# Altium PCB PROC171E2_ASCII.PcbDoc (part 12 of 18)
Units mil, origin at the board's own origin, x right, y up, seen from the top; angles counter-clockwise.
Board outline 7700 x 2300 mil, 6 copper layers (Top Layer, GND 1, SIG 1, SIG 2, GND 2, Bottom Layer), stack 61.062 mil thick; 938 components, 688 nets, 11933 pads, 1723 vias.
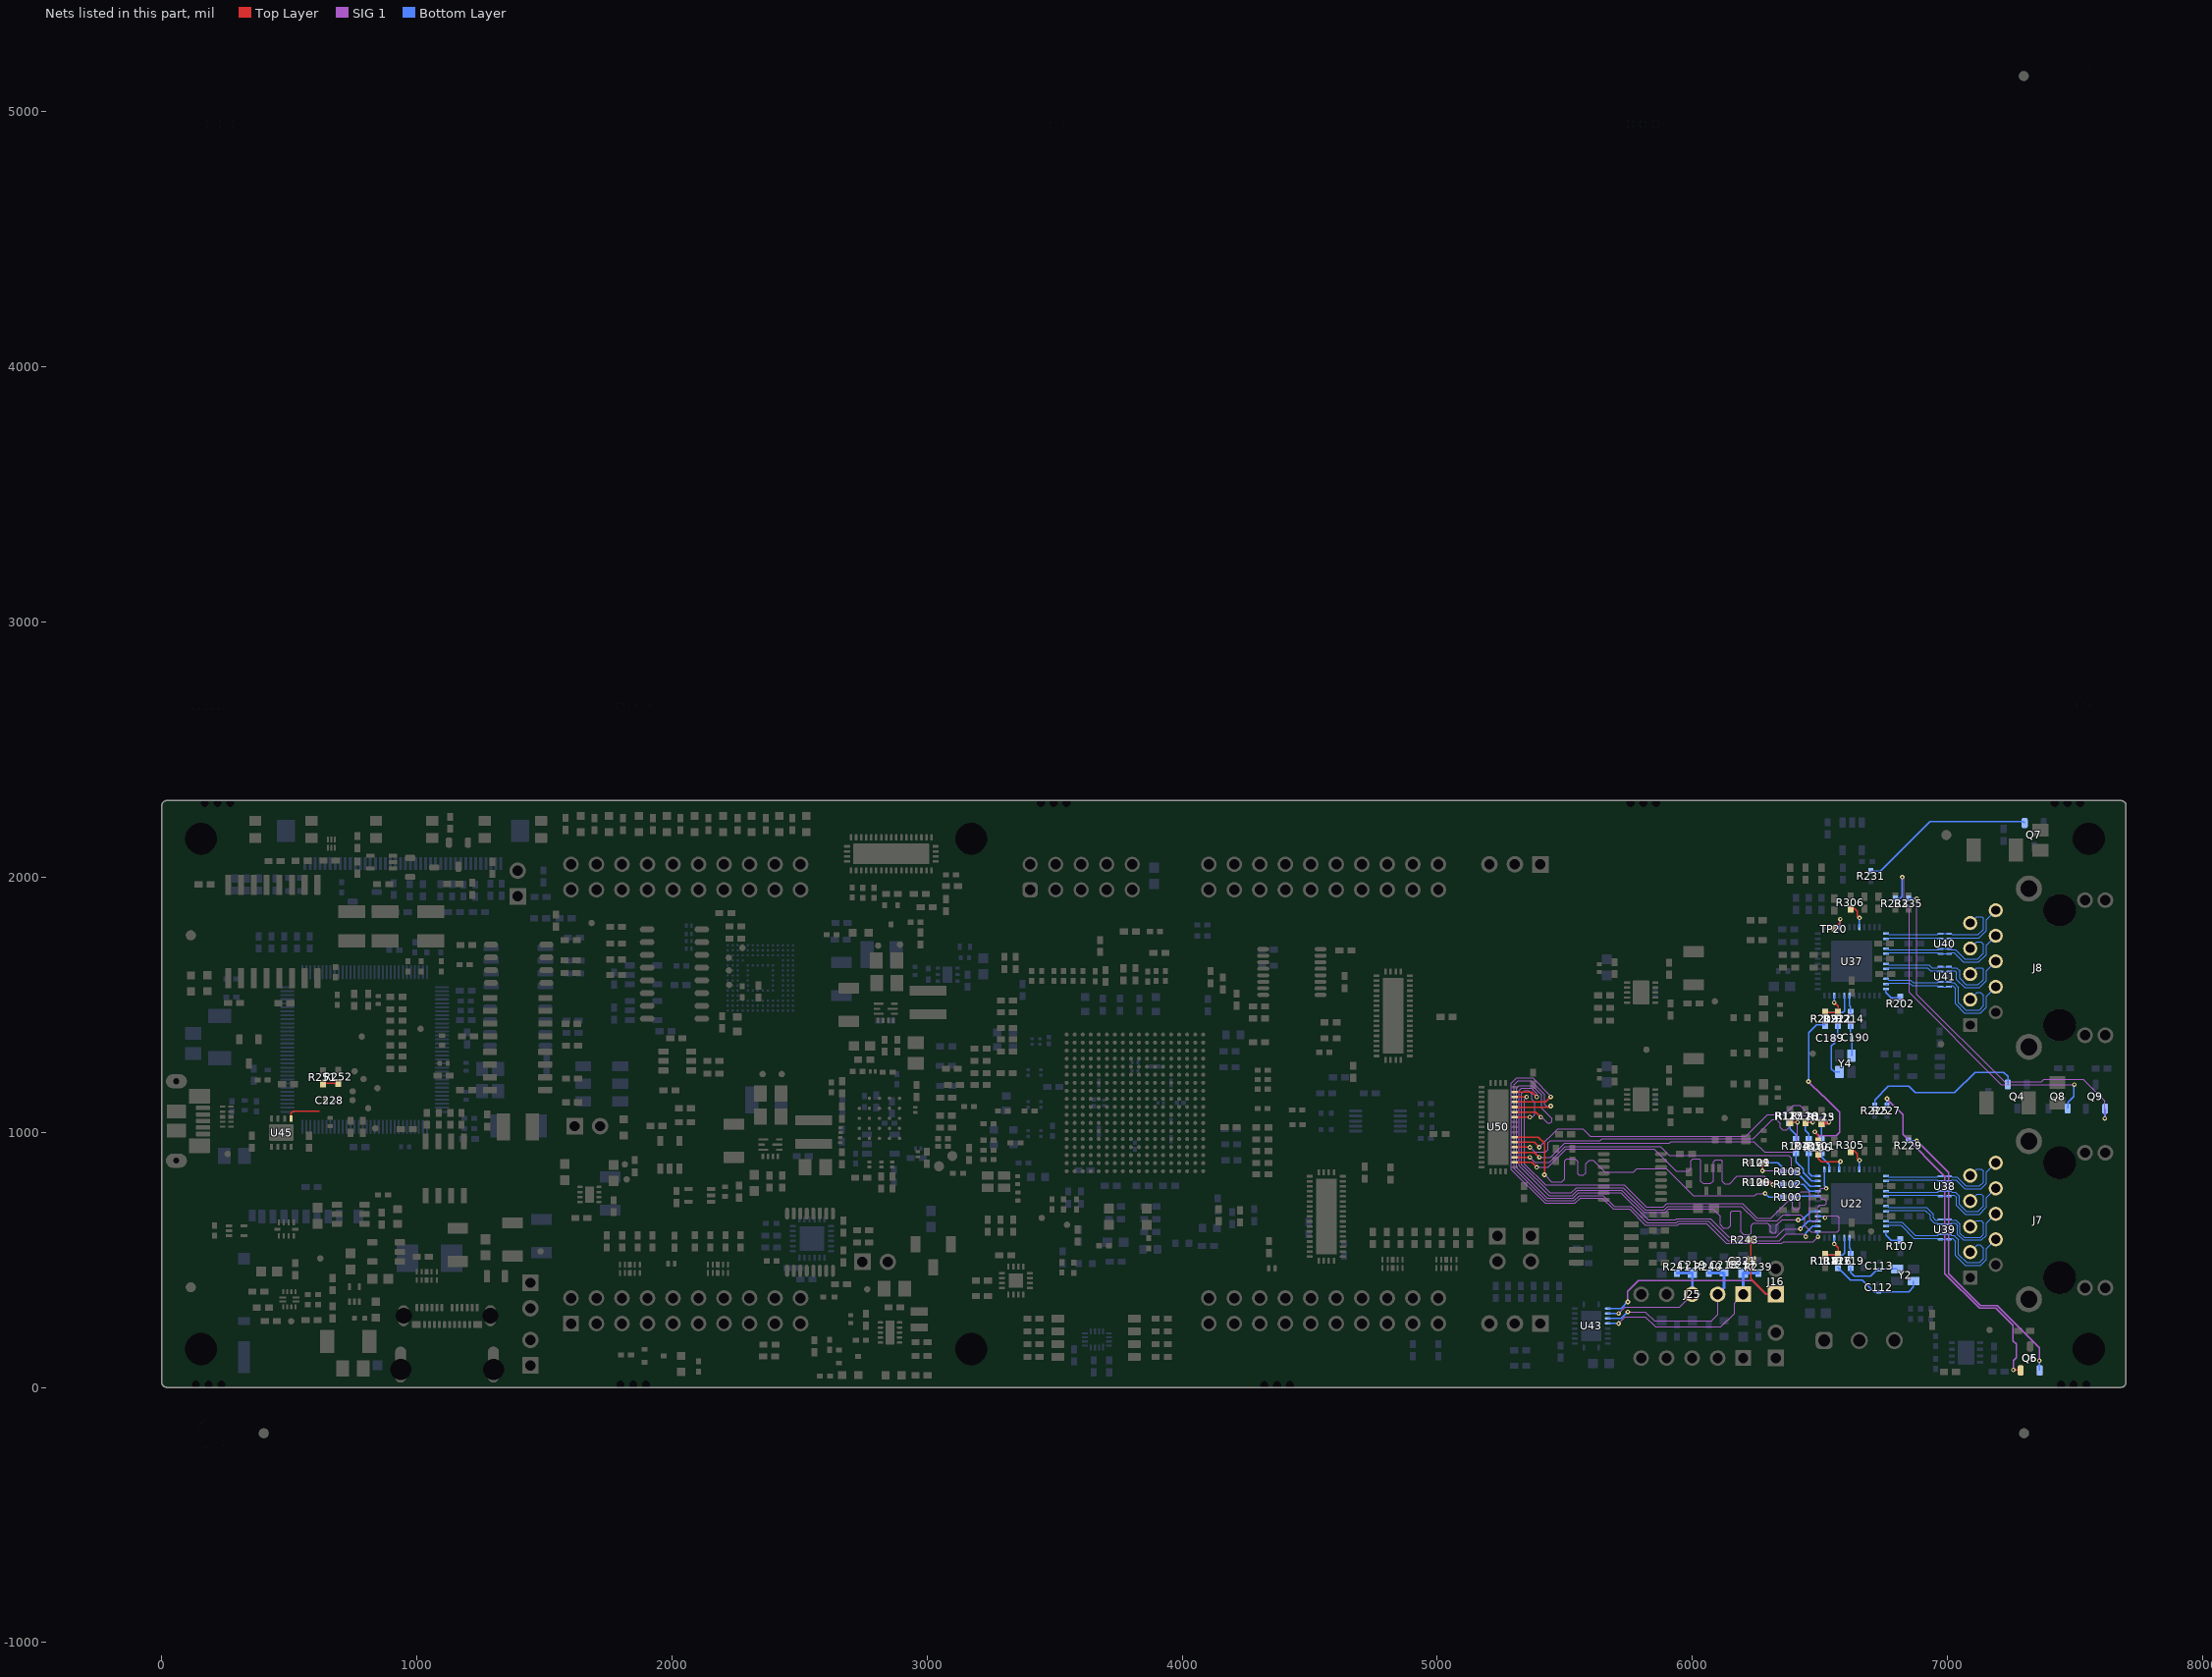
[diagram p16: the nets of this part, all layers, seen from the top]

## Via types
v1: diameter 18, hole 8, Top Layer to Bottom Layer, tented both sides, 1592 vias
v2: diameter 19.68, hole 7.87, Top Layer to Bottom Layer, tented both sides, 104 vias
v3: diameter 19.68, hole 7.87, Top Layer to Bottom Layer, 24 vias
v4: diameter 18, hole 8, Top Layer to Bottom Layer, 3 vias

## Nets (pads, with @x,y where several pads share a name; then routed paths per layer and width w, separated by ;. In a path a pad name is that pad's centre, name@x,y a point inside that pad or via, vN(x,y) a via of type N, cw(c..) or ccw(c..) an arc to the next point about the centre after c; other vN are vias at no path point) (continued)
EQEP2_A: C217.1 J25.1 R239.1 U43.15 | length 777.5
  SIG 1 w4.75: v1(5710.83,250.47) 5735.98,275.62 5816.23,275.62 5855,236.85 6111.85,236.85 6165,290 6165,330.82 J25.1@6199.18,365
  Bottom Layer w5.3: U43.15@5668.62,250.47 v1(5710.83,250.47)
  Bottom Layer w10: J25.1@6199.18,365 C217.1@6199.18,448.5 R239.1@6259.18,448.5
EQEP2_B: C218.2 J25.2 R240.1 U43.14 | length 700.2
  SIG 1 w4.75: v1(5746.83,295.74) 5816.12,295.74 5851.86,260 6074.18,260 6099.18,285 J25.2@6099.18,365
  Bottom Layer w5.3: U43.14@5668.62,270.15 5721.24,270.15 v1(5746.83,295.74)
  Bottom Layer w10: R240.1@6064.18,448.5 6124.18,448.5 6124.18,390 J25.2@6099.18,365
EQEP2_INDEX: C219.1 J25.3 R241.1 U43.13 | length 505.8
  SIG 1 w4.75: v1(5710.83,289.84) 5736.25,315.27 5754.91,315.27 5755.18,315 5949.18,315 J25.3@5999.18,365
  Bottom Layer w5.3: U43.13@5668.62,289.84 v1(5710.83,289.84)
  Bottom Layer w10: R241.1@5940,448.5 C219.1@6000,448.5 6000,365.82 J25.3@5999.18,365
EQEP2_STROBE: C221.1 J16.1 R243.1 U43.12 | length 1026.2
  Top Layer w5.3: R243.1@6228.62,578.2 C221.1@6228.62,494.67 6228.62,426.16 6289.78,365 J16.1@6327.06,365
  SIG 1 w5.3: v1(5746.83,335.11) 5746.83,376.91 5788.61,418.7 6234.98,418.7 6288.68,365 J16.1@6327.06,365
  Bottom Layer w5.3: U43.12@5668.62,309.52 5721.24,309.52 v1(5746.83,335.11)
ETH1_CLKOUT: R106.2 R213.1 | length 674.4
  Top Layer w5.3: v1(6480,1001.54) 6492.48,989.06 6492.48,964.89 R106.2@6493.31,964.06
  SIG 1 w5.3: v1(6455,1198.82) 6455,1198.58 6511.01,1142.57 6514.26,1142.57 6578.11,1078.71 6578.11,999.23 6564.36,985.48 6496.06,985.48 v1(6480,1001.54)
  Bottom Layer w5.3: v1(6455,1198.82) 6456.28,1200.09 6456.28,1390.04 6487.61,1421.38 R213.1@6520,1421.38
ETH1_CLKOUT_R: R106.1 U22.40 | length 143.4
  Top Layer w5.3: R106.1@6493.31,916.82 6493.31,898.47 6506.77,885 v1(6580,885)
  Bottom Layer w5.3: U22.40@6575.96,853.9 6575.96,880.96 v1(6580,885)
ETH1_GPIO_1: R114.1 R126.2 U22.22 | length 124.8
  Top Layer w5.3: R114.1@6520,518.62 R126.2@6570.85,518.62 6570.97,518.5 6570.97,547.55 v1(6556.28,562.25)
  Bottom Layer w5.3: v1(6556.28,562.25) U22.22@6556.28,586.18
ETH1_LED0: Q5.1 R227.1 | length 1372.2
  Top Layer w5.3: v1(7257.91,68.45) 7284.56,68.45 Q5.1@7286.6,66.42
  SIG 1 w5.3: v1(6762.73,1131.46) 6825.85,1068.34 6825.85,991.55 6990,827.4 6990,445.22 7124.89,310.33 7190,310.33 7257.23,243.1 7257.23,181.91 7269.52,169.62 7269.52,117.13 7257.91,105.52 v1(7257.91,68.45)
  Bottom Layer w5.3: R227.1@6762.73,1104.68 v1(6762.73,1131.46)
ETH1_LED1: Q6.1 R229.1 | length 1171.5
  SIG 1 w5.3: v1(6880,966.71) 7005,841.71 7005,445.21 7129.28,320.92 7194.39,320.92 7360,155.32 v1(7360,105)
  Bottom Layer w5.3: R229.1@6846.59,967.35 6879.36,967.35 v1(6880,966.71) ; v1(7360,105) 7361.4,103.6 Q6.1@7361.4,66.42
ETH1_LED2: Q4.1 R225.1 | length 647.5
  Bottom Layer w5.3: R225.1@6715,1104.31 6715,1126.37 6768.63,1180 6849.04,1180 6874,1155.04 7028.54,1155.04 7108.38,1234.88 7220.44,1234.88 7236.69,1218.62 Q4.1@7236.69,1187.24
ETH1_PWDN: R305.2 U22.44 | length 96.3
  Top Layer w5.3: R305.2@6620,926.46 6635.61,926.46 6647.07,915 6647.07,897.93 v1(6655,890)
  Bottom Layer w5.3: U22.44@6654.7,853.9 6654.7,889.7 v1(6655,890)
ETH1_RBIAS: R107.2 U22.12 | length 78.8
  Bottom Layer w5.3: U22.12@6759.03,611.77 6759.03,597.39 6779.43,576.99 R107.2@6815,576.99
ETH1_RD0: R102.1 R108.1 R120.2 U50.2 | length 1562.3
  Top Layer w5.3: U50.2@5303.35,882.24 5370.31,882.24 v1(5390,862.56) ; R108.1@6274.92,802.65 6307.35,802.65 v1(6315,795)
  SIG 1 w4.75: v1(5390,862.56) 5434.78,862.56 5506.27,934.04 5849.85,934.04 5936.89,847 5984.43,847 5995,857.58 5995,887.63 6002.37,895 6027,895 6033.5,888.5 6033.5,808 6042,799.5 6072,799.5 6082.5,810 6082.5,884.31 6090,891.81 6111.9,891.81 6118.31,885.4 6118.31,807.56 6127.58,798.29 6145.75,798.29 6175.76,828.31 6281.69,828.31 v1(6315,795)
  Bottom Layer w5.3: R120.2@6274.92,802.65 6305.55,802.65 6313.2,795 v1(6315,795) ; v1(6315,795) v1(6315,795) ; v1(6315,795) v1(6315,795) ; v1(6315,795) R102.1@6351.89,795.04 v1(6315,795)
ETH1_RD0_R: R102.2 U22.33 | length 102.9
  Bottom Layer w5.3: R102.2@6399.14,795.04 6434.21,795.04 6460,769.25 U22.33@6491.32,769.25
ETH1_RD1: R103.1 R109.1 R121.2 U50.3 | length 1461.1
  Top Layer w5.3: U50.3@5303.35,901.93 v1(5363,901.93) ; v1(6274.92,848.96) 6275,849.04 R109.1@6275,880.96
  SIG 1 w4.75: v1(5363,901.93) 5382.25,882.68 5440.3,882.68 5501.72,944.09 5875.18,944.09 5910,909.28 6376.47,909.28 6387.88,897.87 6387.88,857.13 6379.71,848.96 v1(6274.92,848.96)
  Bottom Layer w5.3: v1(6274.92,848.96) 6275,849.04 6275,880.96 R121.2@6275.11,880.85 6335,880.85 6351.89,863.96 R103.1@6351.89,845.04
ETH1_RD1_R: R103.2 U22.34 | length 115.4
  Bottom Layer w5.3: R103.2@6399.14,845.04 6408.3,835.88 6414.87,835.88 6461.81,788.94 U22.34@6491.32,788.94
ETH1_RD2: R104.1 R115.1 R127.2 U50.4 | length 1405.3
  Top Layer w5.3: U50.4@5303.35,921.61 5380.31,921.61 v1(5400,901.93) ; R115.1@6383.01,1039.34 6411.64,1039.34 v1(6411.73,1039.27)
  SIG 1 w4.75: v1(5400,901.93) 5444.28,901.93 5500,957.65 5910.18,957.65 5916.61,964.08 6240.92,964.08 6283.23,921.77 6394.93,921.77 6411.73,938.57 v1(6411.73,1039.27)
  Bottom Layer w5.3: R104.1@6406.28,968.62 6406.28,990.72 6383.01,1013.99 6383.01,1039.35 6411.65,1039.35 v1(6411.73,1039.27)
ETH1_RD2_R: R104.2 U22.35 | length 161.9
  Bottom Layer w5.3: R104.2@6406.28,921.38 6406.28,883.72 6434.51,855.49 6434.51,841.68 6467.57,808.62 U22.35@6491.32,808.62
ETH1_RD3: R105.1 R116.1 R128.2 U50.5 | length 1451.1
  Top Layer w5.3: U50.5@5303.35,941.3 v1(5363,941.3) ; R116.1@6443.01,1039.35 v1(6471.73,1039.27) v1(6471.73,1039.27)
  SIG 1 w4.75: v1(5363,941.3) 5382.52,921.77 5425,921.77 5435,931.77 5435,959.08 5443.62,967.7 5638.89,967.7 5645.32,974.13 6213.36,974.13 6237.72,974.13 6313.59,1050 6329.53,1050 6345,1034.53 6345,1019.23 6354.23,1010 6370.2,1010 6380,1019.8 6380,1040.56 6405.24,1065.8 6445.2,1065.8 v1(6471.73,1039.27)
  Bottom Layer w5.3: R105.1@6456.28,968.62 6456.28,993.72 6443.01,1006.99 R128.2@6443.01,1039.35 v1(6471.73,1039.27) v1(6471.73,1039.27)
ETH1_RD3_R: R105.2 U22.36 | length 121.1
  Bottom Layer w5.3: R105.2@6456.28,921.38 6456.28,840.34 6468.31,828.31 U22.36@6491.32,828.31
ETH1_RX_CTL: R101.1 R113.1 R125.2 U50.6 | length 1489.3
  Top Layer w5.3: U50.6@5303.35,960.98 5380.31,960.98 v1(5400,941.3)
  Top Layer w15: R113.1@6506.28,1036.06 6530.9,1036.06 6534.27,1039.43 6534.92,1039.43 v1(6535,1039.35)
  SIG 1 w4.75: v1(5400,941.3) 5471.99,1013.28 5570,1013.28 5599.1,984.18 5740,984.18 6209.2,984.18 6293.59,1068.57 6360,1068.57 6397.19,1105.76 6421.29,1105.76 6467.71,1059.35 6515,1059.35 v1(6535,1039.35)
  Bottom Layer w5.3: R101.1@6506.28,968.62 R125.2@6506.28,1036.06 6506.28,1039.43 6534.92,1039.43 v1(6535,1039.35)
ETH1_RX_CTL_R: R101.2 U22.38 | length 80
  Bottom Layer w5.3: R101.2@6506.28,921.38 6506.28,902.66 6536.59,872.35 U22.38@6536.59,853.9
ETH1_RXC: R100.1 U50.7 | length 1448.9
  Top Layer w5.3: U50.7@5303.35,980.67 5395.9,980.67 5420,956.57 v1(5420,833.39)
  SIG 1 w4.75: v1(5420,833.39) 5448.39,805 5487.57,805 5499.83,817.26 5499.83,888.13 5506.7,895 5540,895 5550.88,884.12 5550.88,836.51 5555,832.4 5573.7,832.4 5582.03,840.72 5582.03,876.84 5595.19,890 5611.43,890 5657.06,844.36 5769.87,844.36 5782.78,857.27 5898.2,857.27 6003.99,751.48 6244.48,751.48 6253,760 v1(6285.22,760)
  Bottom Layer w5.3: v1(6285.22,760) 6300.18,745.04 R100.1@6351.89,745.04
ETH1_RXC_R: R100.2 U22.32 | length 94.1
  Bottom Layer w5.3: R100.2@6399.14,745.04 6403.66,749.57 U22.32@6491.32,749.57
ETH1_TD0: U22.28 U50.11 | length 2055
  Top Layer w5.3: U50.11@5303.35,1059.41 v1(5363,1059.41)
  SIG 1 w4.75: v1(5363,1059.41) 5364.94,1061.34 5374.37,1061.34 5382.82,1069.8 5382.82,1115.6 5370.75,1127.67 5370.75,1149.62 5357.34,1163.03 5342.66,1163.03 5330.75,1151.12 5330.75,873.2 5441.53,762.42 5524.44,762.42 5545.16,783.13 5727.91,783.13 5814.73,696.31 5890,696.31 5903.54,709.85 6192.9,709.85 6249.72,653.03 6333.71,653.03 6356.4,675.72 6422.97,675.72 6440,658.7 6440,635 6465,610 6567.94,610 6575,617.06 6575,665.16 6567.18,672.98 6528.11,672.98 6520.13,665 v1(6520,665)
  Bottom Layer w5.3: U22.28@6491.32,670.83 6514.17,670.83 v1(6520,665)
ETH1_TD1: U22.27 U50.12 | length 2056
  Top Layer w5.3: U50.12@5303.35,1079.09 5386.14,1079.09 v1(5405.83,1059.41)
  SIG 1 w4.75: v1(5405.83,1059.41) 5408.96,1059.41 5433.03,1035.33 5442.03,1035.33 5449.22,1042.52 5449.22,1054.14 5409.52,1093.84 5409.52,1145.84 5372.24,1183.13 5320.28,1183.13 5310.65,1173.51 5310.65,862.02 5430.72,741.96 5532.4,741.96 5553.06,762.62 5720,762.62 5826.07,656.55 5934.66,656.55 5939.11,661 6071.8,661 6142.8,590 6329.24,590 6360.49,621.24 v1(6423.51,621.24)
  Bottom Layer w5.3: v1(6423.51,621.24) 6453.41,651.14 U22.27@6491.32,651.14
ETH1_TD2: U22.26 U50.13 | length 2055.5
  Top Layer w5.3: U50.13@5303.35,1098.78 5440.96,1098.78 v1(5444.69,1102.5)
  SIG 1 w4.75: v1(5444.69,1102.5) 5427.5,1102.5 5420,1110 5420,1149.11 5419.57,1149.54 5419.57,1150.01 5367.01,1202.57 5316.69,1202.57 5300.6,1186.48 5300.6,857.86 5426.55,731.91 5536.57,731.91 5556.84,752.17 5650.19,752.17 5693.4,708.96 5716.69,708.96 5716.75,708.9 5757.26,708.9 5816.45,649.71 5818.69,649.71 5821.91,646.5 5938.82,646.5 5943.27,650.95 6064.05,650.95 6140.7,574.3 6341.05,574.3 6367.3,600.55 6434.76,600.55 v1(6444.47,590.85)
  Bottom Layer w5.3: v1(6444.47,590.85) 6444.47,605 6470.92,631.46 U22.26@6491.32,631.46
ETH1_TD3: U22.25 U50.14 | length 2057.9
  Top Layer w5.3: U50.14@5303.35,1118.46 5424.41,1118.46 v1(5444.69,1138.73)
  SIG 1 w4.75: v1(5444.69,1138.73) 5444.69,1142.55 5374.62,1212.62 5311.94,1212.62 5290.55,1191.23 5290.55,853.7 5422.39,721.86 5540.73,721.86 5561,742.12 5646.02,742.12 5689.24,698.91 5712.52,698.91 5712.58,698.85 5753.1,698.85 5815.5,636.45 5942.98,636.45 5947.44,640.9 6055.5,640.9 6132.15,564.25 6350.44,564.25 6357.43,571.24 6473.4,571.24 v1(6492.17,590)
  Bottom Layer w5.3: U22.25@6491.32,611.77 6491.32,590.85 v1(6492.17,590)
ETH1_TD_A_N: J7.10 U22.2 U38.2 U38.9 | length 517.6
  Bottom Layer w4: U22.2@6759.03,808.62 6766.12,808.62 6770.11,812.61 6960.13,812.61 6964.12,808.62 U38.9@6973.14,808.62 U38.2@7006.02,808.62 7013.2,808.62 7017.19,812.61 7032.5,812.61 7067.37,777.74 7130.85,777.74 7152.19,799.09 7152.19,843.12 J7.10@7189.08,880
ETH1_TD_A_P: J7.9 U22.1 U38.1 U38.10 | length 515.8
  Bottom Layer w4: U22.1@6759.03,828.31 6766.12,828.31 6770.11,824.31 6960.13,824.31 6964.12,828.31 U38.10@6973.14,828.31 U38.1@7006.02,828.31 7013.2,828.31 7017.19,824.31 7037.35,824.31 7072.22,789.44 7126.01,789.44 7140.49,803.93 7140.49,848.4 7133.9,855 7114.08,855 J7.9@7089.08,830
ETH1_TD_B_N: J7.8 U22.5 U38.5 U38.6 | length 547.5
  Bottom Layer w4: U22.5@6759.03,749.57 6766.12,749.57 6770.11,753.56 6944.85,753.56 6961.96,753.56 6965.96,749.57 U38.6@6973.14,749.57 U38.5@7006.02,749.57 7013.2,749.57 7017.19,753.56 7026.59,753.56 7035,745.15 7035,713.9 7069.86,679.04 7124.85,679.04 7152.19,706.39 7152.19,743.12 J7.8@7189.08,780
ETH1_TD_B_P: J7.7 U22.4 U38.4 U38.7 | length 549.1
  Bottom Layer w4: U22.4@6759.03,769.25 6766.12,769.25 6770.11,765.26 6940,765.26 6961.96,765.26 6965.96,769.25 U38.7@6973.14,769.25 U38.4@7006.02,769.25 7013.2,769.25 7017.19,765.26 7031.44,765.26 7046.7,750 7046.7,717.26 7073.22,690.74 7120,690.74 7140.49,711.23 7140.49,749.07 7132.02,757.54 7116.62,757.54 J7.7@7089.08,730
ETH1_TD_C_N: J7.6 U22.8 U39.2 U39.9 | length 581.5
  Bottom Layer w4: U22.8@6759.03,690.51 6766.12,690.51 6770.11,694.5 6912.47,694.5 6933.04,673.94 6933.04,659.43 6948.47,644 6960.97,644 6965.69,639.28 U39.9@6972.87,639.28 U39.2@7005.75,639.28 7012.93,639.28 7016.92,643.28 7030.57,643.28 7039.7,634.15 7039.7,600.15 7062.15,577.7 7133.36,577.7 7152.19,596.54 7152.19,643.12 J7.6@7189.08,680
ETH1_TD_C_P: J7.5 U22.7 U39.1 U39.10 | length 581.5
  Bottom Layer w4: U22.7@6759.03,710.2 6766.12,710.2 6770.11,706.2 6917.32,706.2 6944.74,678.78 6944.74,664.27 6953.31,655.7 6962.42,655.7 6965.69,658.97 U39.10@6972.87,658.97 U39.1@7005.75,658.97 7012.93,658.97 7016.92,654.98 7034.02,654.98 7049,640 7049,604 7066,587 7129.5,587 7142,599.5 7142,643.67 7133.26,652.41 7111.49,652.41 J7.5@7089.08,630
ETH1_TD_D_N: J7.4 U22.11 U39.5 U39.6 | length 600.5
  Bottom Layer w4: U22.11@6759.03,631.46 6766.12,631.46 6770.11,635.45 6817.1,635.45 6868.33,584.22 6961.69,584.22 6965.69,580.23 U39.6@6972.87,580.23 U39.5@7005.75,580.23 7012.93,580.23 7016.92,584.22 7020.52,584.22 7031.57,573.18 7031.57,516.63 7070.15,478.05 7129.73,478.05 7152.19,500.51 7152.19,543.12 J7.4@7189.08,580
ETH1_TD_D_P: J7.3 U22.10 U39.4 U39.7 | length 600.3
  Bottom Layer w4: U22.10@6759.03,651.14 6766.12,651.14 6770.11,647.15 6821.94,647.15 6873.17,595.92 6961.69,595.92 6965.69,599.91 U39.7@6972.87,599.91 U39.4@7005.75,599.91 7012.93,599.91 7016.92,595.92 7025.37,595.92 7043.27,578.02 7043.27,521.48 7075,489.75 7124.88,489.75 7140.49,505.36 7140.49,546.37 7128.62,558.25 7117.33,558.25 J7.3@7089.08,530
ETH1_TX_CTL_EN: U22.37 U50.15 | length 2054.8
  Top Layer w5.3: U50.15@5303.35,1138.15 v1(5350,1138.15)
  SIG 1 w4.75: v1(5350,1138.15) 5342.66,1130.81 5342.66,875.5 5424.98,793.18 5732.07,793.18 5818.89,706.36 5885.84,706.36 5899.38,719.9 6197.07,719.9 6253.88,663.08 6307.97,663.08 6375.43,730.54 6386.38,730.54 6392.27,724.65 6392.27,704.92 6399.07,698.12 6414.84,698.12 6420.75,704.04 6420.75,760.89 6426.89,767.03 6454.01,767.03 6460,761.04 6460,658.09 6468.78,649.3 6481.42,649.3 6490.33,658.21 6490.33,705 6500.33,715 6518.83,715 6525,721.17 6525,730.54 6516.85,738.69 6505.88,738.69 6494.01,750.56 6494.01,769.01 6505,780 v1(6525,780)
  Bottom Layer w5.3: U22.37@6516.91,853.9 6516.91,789.45 6525,781.36 v1(6525,780)
ETH1_TXC: U22.29 U50.16 | length 2055.5
  Top Layer w5.3: U50.16@5303.35,1157.83 5370.31,1157.83 v1(5390,1138.15)
  SIG 1 w4.75: v1(5390,1138.15) 5390,1151.16 5368.07,1173.08 5330.84,1173.08 5320.7,1162.95 5320.7,869.04 5437.37,752.37 5528.6,752.37 5549.32,773.08 5723.75,773.08 5810.57,686.26 5894.16,686.26 5907.7,699.8 6080.39,699.8 6110,670.19 6110,637.01 6122.01,625 6141,625 6150,634 6150,685.95 6155.08,691.04 6185.3,691.04 6190,686.33 6190,610 6199.95,600.05 6225,600.05 6230,605.05 6230,635 6237.98,642.98 6293.59,642.98 6305.61,630.97 6305.61,611.55 6311.59,605.56 6324.47,605.56 6330,611.09 6330,635.11 6351.36,656.47 v1(6415,656.47)
  Bottom Layer w5.3: v1(6415,656.47) 6431.61,656.47 6465.64,690.51 U22.29@6491.32,690.51
ETH1_XI: R117.2 R118.2 U22.20 | length 139
  Bottom Layer w5.3: R118.2@6520,518.62 6588.54,518.62 6595.65,525.73 U22.20@6595.65,586.18
ETH1_XO: R119.2 U22.19 | length 69.5
  Bottom Layer w5.3: U22.19@6615.33,586.18 6615.33,546.87 6620,542.2 R119.2@6620,518.62
ETH1_XTAL_XI: C112.2 R117.1 Y2.1 | length 367.8
  Bottom Layer w5.3: R117.1@6570,471.38 6620,421.38 6666.07,421.38 6712.42,375.02 C112.2@6730.7,375.02 6848.57,375.02 6866.59,393.03 Y2.1@6866.59,416.88
ETH1_XTAL_XO: C113.2 R119.1 Y2.3 | length 221.6
  Bottom Layer w5.3: R119.1@6620,471.38 6620,450.76 6634.18,436.58 6699.09,436.58 6728.01,465.5 6729.39,464.12 Y2.3@6802.61,464.12
ETH2_CLKOUT: TP20.1 U37.40 | length 80.9
  Top Layer w5.3: TP20.1@6555,1797.09 6579.77,1821.86 6579.77,1834.88 v1(6579.61,1835.03)
  Bottom Layer w5.3: U37.40@6575.96,1803.9 6577.79,1805.72 6577.79,1833.21 v1(6579.61,1835.03)
ETH2_GPIO_1: R209.1 R221.2 U37.22 | length 124.8
  Top Layer w5.3: R209.1@6520,1468.62 6570.85,1468.62 R221.2@6570.97,1468.5 6570.97,1493.56 v1(6556.28,1508.25)
  Bottom Layer w5.3: v1(6556.28,1508.25) U37.22@6556.28,1536.18
ETH2_LED0: Q8.1 R233.1 | length 1470.4
  SIG 1 w4.75: v1(6822.8,2000) 6828.75,1994.05 6828.75,1906.25 6850,1885 6850,1547.71 7210.75,1186.96 v1(7497.11,1186.96)
  Bottom Layer w5.3: R233.1@6795,1916.06 6813.2,1916.06 6822.14,1925 6822.14,1999.34 v1(6822.8,2000) ; Q8.1@7471.27,1093.42 7471.27,1116.69 7494.46,1139.88 7494.46,1180.87 7497.11,1183.52 v1(7497.11,1186.96)
ETH2_LED1: Q9.1 R235.1 | length 1433.7
  SIG 1 w4.75: v1(6880,1916.06) 6880,1540.66 7223.65,1197.01 7367.31,1197.01 7377.27,1206.97 7533.03,1206.97 7534.42,1205.58 7616.46,1123.54 v1(7616.46,1053.72)
  Bottom Layer w5.3: R235.1@6848,1916.06 v1(6880,1916.06) ; v1(7616.46,1053.72) 7617.73,1055 Q9.1@7617.73,1092.15
ETH2_LED2: Q7.1 R231.1 | length 685.1
  Bottom Layer w5.3: R231.1@6700,2024.37 6737.01,2024.37 6930.56,2217.92 7296.93,2217.92 Q7.1@7302.6,2212.24
ETH2_PWDN: R306.2 U37.44 | length 96.3
  Top Layer w5.3: R306.2@6620,1876.46 6635.61,1876.46 6647.07,1865 6647.07,1847.93 v1(6655,1840)
  Bottom Layer w5.3: U37.44@6654.7,1803.9 6654.7,1839.7 v1(6655,1840)
ETH2_RBIAS: R202.2 U37.12 | length 78.8
  Bottom Layer w5.3: U37.12@6759.03,1561.77 6759.03,1547.39 6779.43,1526.99 R202.2@6815,1526.99
ETH2_TD_A_N: J8.10 U37.2 U40.2 U40.9 | length 504.6
  Bottom Layer w4: U37.2@6759.03,1758.62 6766.12,1758.62 6770.11,1762.61 6937.42,1762.61 6961.96,1762.61 6965.96,1758.62 U40.9@6973.14,1758.62 U40.2@7006.02,1758.62 7013.2,1758.62 7017.19,1762.61 7124.55,1762.61 7152.19,1790.26 7152.19,1833.12 J8.10@7189.08,1870
ETH2_TD_A_P: J8.9 U37.1 U40.1 U40.10 | length 503.5
  Bottom Layer w4: U37.1@6759.03,1778.31 6766.12,1778.31 6770.11,1774.31 6932.57,1774.31 6961.96,1774.31 6965.96,1778.31 U40.10@6973.14,1778.31 U40.1@7006.02,1778.31 7013.2,1778.31 7017.19,1774.31 7119.71,1774.31 7140.49,1795.1 7140.49,1839.51 7135,1845 7114.08,1845 J8.9@7089.08,1820
ETH2_TD_B_N: J8.8 U37.5 U40.5 U40.6 | length 514.4
  Bottom Layer w4: U37.5@6759.03,1699.57 6766.12,1699.57 6770.11,1703.56 6956.02,1703.56 6961.96,1703.56 6965.96,1699.57 U40.6@6973.14,1699.57 U40.5@7006.02,1699.57 7013.2,1699.57 7017.19,1703.56 7026.57,1703.56 7063.16,1666.97 7122.78,1666.97 7152.19,1696.39 7152.19,1733.12 J8.8@7189.08,1770
ETH2_TD_B_P: J8.7 U37.4 U40.4 U40.7 | length 513
  Bottom Layer w4: U37.4@6759.03,1719.25 6766.12,1719.25 6770.11,1715.26 6951.17,1715.26 6961.96,1715.26 6965.96,1719.25 U40.7@6973.14,1719.25 U40.4@7006.02,1719.25 7013.2,1719.25 7017.19,1715.26 7031.41,1715.26 7068,1678.67 7117.93,1678.67 7140.49,1701.23 7140.49,1737.35 7132.05,1745.8 7114.19,1745.8 7089.08,1720.68 J8.7@7089.08,1720
ETH2_TD_C_N: J8.6 U37.8 U41.2 U41.9 | length 549.3
  Bottom Layer w4: U37.8@6759.03,1640.51 6766.12,1640.51 6770.11,1644.5 6922.46,1644.5 6933.69,1633.28 6961.69,1633.28 6965.69,1629.28 U41.9@6972.87,1629.28 U41.2@7005.75,1629.28 7012.93,1629.28 7016.92,1633.28 7030,1633.28 7036.22,1627.06 7036.22,1598.82 7067.89,1567.15 7125.69,1567.15 7152.19,1593.65 7152.19,1633.12 J8.6@7189.08,1670
ETH2_TD_C_P: J8.5 U37.7 U41.1 U41.10 | length 547.9
  Bottom Layer w4: U37.7@6759.03,1660.2 6766.12,1660.2 6770.11,1656.2 6927.31,1656.2 6938.54,1644.98 6961.69,1644.98 6965.69,1648.97 U41.10@6972.87,1648.97 U41.1@7005.75,1648.97 7012.93,1648.97 7016.92,1644.98 7034.85,1644.98 7047.92,1631.9 7047.92,1603.66 7072.73,1578.85 7120.85,1578.85 7140.49,1598.5 7140.49,1639.01 7134.5,1645 7114.08,1645 J8.5@7089.08,1620
ETH2_TD_D_N: J8.4 U37.11 U41.5 U41.6 | length 586.1
  Bottom Layer w4: U37.11@6759.03,1581.46 6766.12,1581.46 6770.11,1585.45 6850,1585.45 6861.23,1574.22 6961.69,1574.22 6965.69,1570.23 U41.6@6972.87,1570.23 U41.5@7005.75,1570.23 7012.93,1570.23 7016.92,1574.22 7020.52,1574.22 7031.57,1563.18 7031.57,1502.89 7066.42,1468.05 7129.73,1468.05 7152.19,1490.51 7152.19,1533.12 J8.4@7189.08,1570
ETH2_TD_D_P: J8.3 U37.10 U41.4 U41.7 | length 585.4
  Bottom Layer w4: U37.10@6759.03,1601.14 6766.12,1601.14 6770.11,1597.15 6854.85,1597.15 6866.07,1585.92 6961.69,1585.92 6965.69,1589.91 U41.7@6972.87,1589.91 U41.4@7005.75,1589.91 7012.93,1589.91 7016.92,1585.92 7025.37,1585.92 7043.27,1568.02 7043.27,1507.74 7071.26,1479.75 7124.88,1479.75 7140.49,1495.36 7140.49,1536.72 7129.83,1547.39 7116.46,1547.39 J8.3@7089.08,1520
ETH2_XI: R212.2 R213.2 U37.20 | length 139
  Bottom Layer w5.3: R213.2@6520,1468.62 R212.2@6570,1468.62 6588.54,1468.62 6595.65,1475.73 U37.20@6595.65,1536.18
ETH2_XO: R214.2 U37.19 | length 69.5
  Bottom Layer w5.3: U37.19@6615.33,1536.18 6615.33,1496.87 6620,1492.2 R214.2@6620,1468.62
ETH2_XTAL_XI: C189.2 R212.1 Y4.1 | length 213.2
  Bottom Layer w5.3: C189.2@6557.12,1370 6557.12,1371.97 6562.35,1377.19 6564.32,1377.19 6570,1382.88 R212.1@6570,1421.38 ; C189.2@6557.39,1362.39 6557.39,1350 6545,1337.61 6545,1248.66 6557.24,1236.42 Y4.1@6576.38,1236.42
ETH2_XTAL_XO: C190.2 R214.1 Y4.3 | length 123.6
  Bottom Layer w5.3: R214.1@6620,1421.38 6620,1375 6625,1370 6625,1301.78 Y4.3@6623.62,1300.4
FB_VDD_XDS3V3: C228.1 R251.1 R252.2 U45.5 | length 195.6
  Top Layer w5.3: U45.5@507.08,1053.44 507.08,1074.16 515.69,1082.78 617.61,1082.78 ; R251.1@631.97,1191.61 690.03,1191.61 R252.2@691.97,1193.54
